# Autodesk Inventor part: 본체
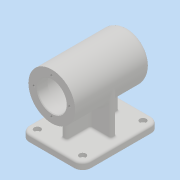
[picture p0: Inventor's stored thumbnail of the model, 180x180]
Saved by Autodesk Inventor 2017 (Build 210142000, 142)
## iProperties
Part Number: 본체
Material: 일반
Document SubType Name: Modeling
Designer: mrc
Density: 1 g/cm^3
Appearance: 기본값
Author: mrc
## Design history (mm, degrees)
sketch "스케치1"
  geometry: L1 (-44, -45)-(44, -45); L2 (56, -33)-(56, 33); L3 (44, 45)-(-44, 45); L4 (-56, 33)-(-56, -33); L5 (-56, -45)-(56, 45); L6 (56, -45)-(-56, 45); C1 r 2.75 at (-44, 33); C2 r 2.75 at (44, 33); C3 r 2.75 at (44, -33); C4 r 2.75 at (-44, -33); A1 r 12 centre (-44, 33) between (-44, 45) and (-56, 33); A2 r 12 centre (44, 33) between (56, 33) and (44, 45); A3 r 12 centre (44, -33) between (44, -45) and (56, -33); A4 r 12 centre (-44, -33) between (-56, -33) and (-44, -45); 1 further point
  constraints: 12 end point, 8 centre point, 8 point on circle, 8 point on line, 8 tangent, 4 coincident, 3 equal radius, 2 midpoint, 2 parallel, 1 horizontal, 1 perpendicular
  dimensions: "d0" = 112 distance of L5.end L6.end; "d1" = 90 distance of L6.end L5.start; "d2" = 12 radius of A1; "d3" = 5.5 diameter of C1; "d4" = 5.5 diameter of C2; "d5" = 5.5 diameter of C3; "d6" = 5.5 diameter of C4
extrude "돌출1" new body sketch "스케치1" distance "d7" = 10; taper "d8" = 0 deg
sketch "스케치3"
  geometry: L1 (33, 0)-(-33, 0) reference; C1 r 34 at (0, 74); 1 further point
  constraints: 1 centre point, 1 vertical alignment
  dimensions: "d9" = 68 diameter of C1; "d10" = 74 distance from line of L1 C1.centre
extrude "돌출2" join sketch "스케치3" stored distance "d11" = 112; taper "d12" = 0 deg
sketch "스케치4"
  geometry: L1 (50, 74)-(-56, 74); L2 (50, 74)-(50, 84.5); L3 (50, 84.5)-(47, 84.5); L4 (47, 84.5)-(47, 90); L5 (47, 90)-(43, 90); L6 (43, 90)-(43, 91.5); L7 (43, 91.5)-(25, 91.5); L8 (25, 91.5)-(25, 95); L9 (25, 95)-(13, 95); L10 (13, 95)-(13, 98); L11 (13, 98)-(-41, 98); L12 (-41, 98)-(-41, 95); L13 (-41, 95)-(-56, 95); L14 (-56, 108)-(-56, 40) reference; L15 (-56, 95)-(-56, 74); 1 further point
  constraints: 28 end point, 11 perpendicular, 1 horizontal, 1 midpoint, 1 point on line, 1 vertical
  dimensions: "d14" = 42 diameter of L13 L1; "d15" = 48 diameter of L11 L1; "d16" = 42 diameter of L9 L1; "d17" = 21 diameter of L3 L1; "d18" = 32 diameter of L5 L1; "d19" = 35 diameter of L7 L1; "d20" = 3 distance between parallel lines of L4 L2; "d21" = 4 distance between parallel lines of L6 L4; "d22" = 18 distance between parallel lines of L8 L6; "d23" = 12 distance between parallel lines of L10 L8; "d24" = 54 distance between parallel lines of L12 L10; "d25" = 15 distance between parallel lines of L14 L12
revolve "회전1" sketch "스케치4" stored, may be unused: angle "d26" = 90 deg
fillet "모깎기1" dims "d27" = 3
fillet "모깎기2" dims "d28" = 3
chamfer "모따기1" distance "d29" = 1; stored, may be unused: second distance "d30" = 2, angle "d31" = 45 deg
fillet "모깎기3" dims "d32" = 10
fillet "모깎기4" dims "d33" = 3
sketch "스케치5"
  geometry: L1 (46, 40)-(-56, 40) reference; L2 (38, 43)-(38, 10); L3 (44, 10)-(-44, 10) reference; L4 (56, 0)-(56, 7) reference; L5 (-56, 0)-(-56, 7) reference; L6 (38, 43)-(-38, 43); L7 (-38, 43)-(-38, 10); L8 (38, 10)-(-38, 10); 1 further point
  constraints: 8 end point, 1 collinear, 1 horizontal, 1 perpendicular, 1 point on line
  dimensions: "d34" = 18 distance between parallel lines of L4 L2; "d36" = 18 distance between parallel lines of L5 L7; "d37" = 3 distance between parallel lines of L1 L6
extrude "돌출3" join sketch "스케치5" stored distance "d38" = 8; taper "d39" = 0 deg
sketch "스케치6"
  geometry: L1 (-34, 52.54)-(-34, 10); L2 (-33, 10)-(33, 10) reference; 1 further point
  constraints: 2 end point, 1 point on line, 1 vertical
  dimensions: "d40" = 34 distance from line of point (0, 0) L1
feature "리브1" sketch "스케치6" dims "d41" = 1, "d42" = 8, "d43" = 0, "d44" = 0, "d45" = 1, "d46" = 1
fillet "모깎기5" dims "d47" = 3
fillet "모깎기6" dims "d48" = 3
fillet "모깎기7" dims "d49" = 3
sketch "스케치7"
  geometry: C1 r 34 at (0, 0) reference; 2 further points
  constraints: 1 horizontal alignment
  dimensions: "d50" = 26 distance of C1.centre point (-26, 0)
hole "구멍1" sketch "스케치7" at (-26, 0) diameter "d51" = 3.242; stored, may be unused: countersink angle "d55" = 90 deg, drill point angle "d57" = 118 deg; dims "d52" = 8, "d53" = 4, "d54" = 2, "d56" = 11
fillet "모깎기8" dims "d61" = 0.3
sketch "스케치8"
  geometry: C1 r 2.75 at (44, -33) reference; C2 r 4.75 at (44, -33); C3 r 2.75 at (-44, -33) reference; C4 r 4.75 at (-44, -33); C5 r 2.75 at (-44, 33) reference; C6 r 4.75 at (-44, 33); C7 r 2.75 at (44, 33) reference; C8 r 4.75 at (44, 33); 1 further point
  constraints: 4 centre point, 4 coincident
  dimensions: "d62" = 9.5 diameter of C2; "d63" = 9.5 diameter of C4; "d64" = 9.5 diameter of C6; "d65" = 9.5 diameter of C8
extrude "돌출4" cut sketch "스케치8" distance "d66" = 5.4; taper "d67" = 0 deg
sketch "스케치9"
  geometry: L1 (100, 0)-(100, 7) reference; 2 further points
  constraints: 1 other
  dimensions: "d68" = 56 distance from line of L1 point (44, 3); "d69" = 3 distance of point (44, 0) point (44, 3)
feature "엠보싱1" sketch "스케치9" dims "d0" = 112, "d1" = 90, "d2" = 12, "d3" = 5.5, "d4" = 5.5, "d5" = 5.5, "d6" = 5.5, "d70" = 0.5, "d71" = 0
node "솔리드1"
mirror "미러1"
pattern_circular "원형 패턴1" dims angle "d59" = 360 deg
